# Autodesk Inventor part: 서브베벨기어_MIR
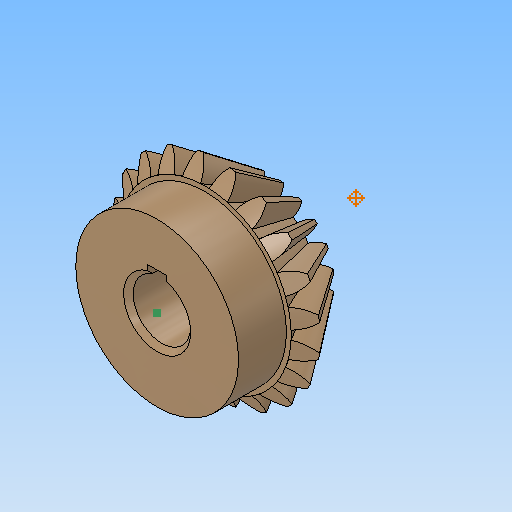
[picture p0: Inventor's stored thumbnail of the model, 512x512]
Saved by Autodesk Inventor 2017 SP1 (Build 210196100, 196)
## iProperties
Created: 2018-09
Part Number: 서브베벨기어_MIR
Material: 강철, 탄소
Document SubType Name: Modeling
Designer: MRC
Categories: <?xml version="1.0" encoding="UTF-16"?> <MemberInstance><Categories><FamilyTemplate><FamilyTemplateParameter ValueType="xs:double" Id="1" ObjectReferenceKey="da
Mass: 135.041 g
Surface Area: 63.6451 cm^2
Volume: 17.1589 cm^3
Density: 7.87 g/cm^3
Appearance: 반광택
d48: 0.000 mm
d49: 0.000 mm
d50: 90.00 deg
d52: 0.000 mm
d53: 0.000 mm
d54: 0.00 deg
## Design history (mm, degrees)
node "서브베벨기어"
  sketch "톱니 본체 스케치"
    geometry: L1 (0, 0)-(-18.003, -31.331) reference; L2 (-18.003, -31.331)-(-21.664, -28.891) reference; L3 (-21.664, -28.891)-(0, 0) reference; L4 (-20, -30)-(0, 0) reference; L5 (-10.813, -18.818)-(-13.012, -17.352) reference; L6 (-18.003, -31.331)-(-10.813, -18.818) reference; L7 (-21.664, -28.891)-(-13.012, -17.352) reference; L8 (0, -39.387)-(0, 6.564) reference; L9 (0, -30)-(-21.664, -30) reference
  sketch "시작 스케치"
    geometry: L1 (0, -23.505)-(0, 10.645) reference; L2 (0.834, -2.928)-(-0.834, -2.928) reference; A1 r 27.357 centre (0, -24.037) between (3.903, 3.04) and (-3.903, 3.04) reference; A2 r 8.898 centre (9.698, -3.713) between (3.903, 3.04) and (0.834, -2.928) reference; A3 r 8.898 centre (-9.698, -3.713) between (-0.834, -2.928) and (-3.903, 3.04) reference; 1 further point
  sketch "끝 스케치"
    geometry: L1 (0, -15.359)-(0, 6.983) reference; L2 (0.497, -1.72)-(-0.497, -1.72) reference; A1 r 16.291 centre (0, -14.29) between (2.324, 1.834) and (-2.324, 1.834) reference; A2 r 5.299 centre (5.775, -2.187) between (2.324, 1.834) and (0.497, -1.72) reference; A3 r 5.299 centre (-5.775, -2.187) between (-0.497, -1.72) and (-2.324, 1.834) reference; 1 further point
  sketch "끝 스케치 오른쪽"
    geometry: L1 (0, -22.649)-(0, 12.15) reference; L2 (0.497, -1.72)-(-0.497, -1.72) reference; A1 r 5.299 centre (5.775, -2.187) between (2.324, 1.834) and (0.497, -1.72) reference; A2 r 5.299 centre (-5.775, -2.187) between (-0.497, -1.72) and (-2.324, 1.834) reference; A3 r 16.291 centre (0, -14.29) between (2.324, 1.834) and (-2.324, 1.834) reference; 1 further point
  sketch "끝 스케치 왼쪽"
    geometry: L1 (0, -35.087)-(0, 18.089) reference; L2 (0.497, -1.716)-(-0.497, -1.716) reference; A1 r 16.291 centre (0, -14.287) between (2.324, 1.838) and (-2.324, 1.838) reference; A2 r 5.299 centre (5.775, -2.183) between (2.324, 1.838) and (0.497, -1.716) reference; A3 r 5.299 centre (-5.775, -2.183) between (-0.497, -1.716) and (-2.324, 1.838) reference; 2 further points; 1 other entity
    constraints: 1 other
  sketch "본체 스케치"
    geometry: L1 (0, -35.038)-(0, -19.531) reference; L2 (-18.003, -31.331)-(-10.813, -18.818) reference; L3 (-10.813, -18.818)-(0, -18.818) reference; L4 (-18.003, -31.331)-(0, -31.331) reference
  sketch "Sketch6"
    geometry: L1 (-20, -30)-(0, 0) reference; L2 (0, -37.8)-(0, 6.3) reference
  sketch "스케치8"
    geometry: C1 r 17 at (0, 0) reference; 1 further point
  sketch "스케치9"
    geometry: 1 further point
  sketch "스케치10"
    geometry: 1 further point
  sketch "스케치11"
    geometry: 1 further point
  sketch "스케치12"
    geometry: L1 (2, 5.657)-(2, 7.8) reference; L2 (2, 7.8)-(-2, 7.8) reference; L3 (-2, 7.8)-(-2, 5.657) reference; A1 r 6 centre (0, 0) between (2, 5.657) and (-2, 5.657) reference; 1 further point
  sketch "3D 스케치 오른쪽"
  sketch "3D 스케치 왼쪽"
  node "메쉬 평면"
  node "맨 위 평면"
  node "톱니 평면"
  node "끝 평면"
  node "끝 평면 왼쪽"
  node "메쉬 평면2"
  node "끝 평면 오른쪽"
  node "Z Axis_1"
  node "맨 위 점"
  node "시작점"
  node "끝점"
feature "Solid1::서브베벨기어"
tag "피쳐 태그1"
node "곡면1"
node "솔리드1"
feature "Srf1::파생"
other parameters: "d48" = 0, "d49" = 0, "d50" = 90 deg, "d52" = 0, "d53" = 0, "d54" = 0 deg
